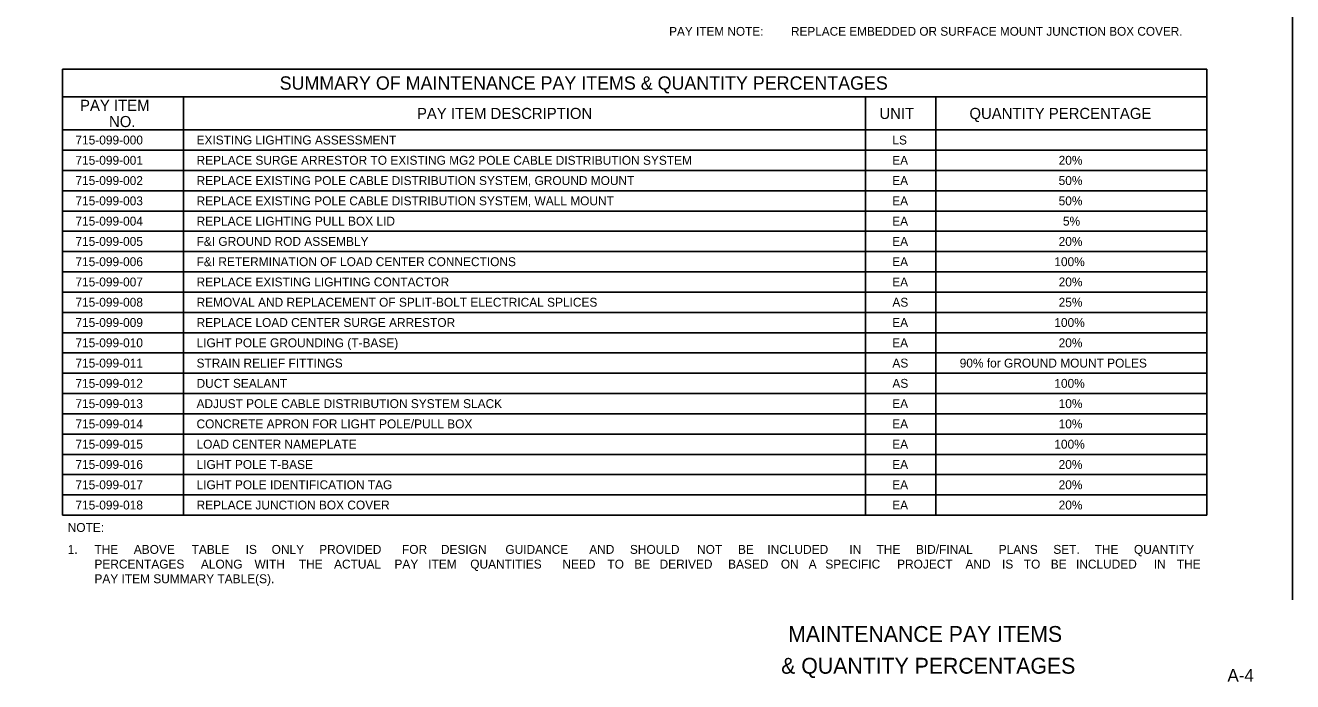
# Model space of a CAD drawing. Extents: x -55 to 2471539, y -90 to 3608906.
# Drawn here: x 543 to 1540, y -64 to 452 of the extents above; entities that cross this region are included whole.
import ezdxf

# ---------------------------------------------------------------- set-up
doc = ezdxf.new("R2010")
doc.units = 0
for name, color, linetype in [('NonPlottingEle_dp', 7, 'Continuous'), ('SumBoxBorder_dp', 7, 'Continuous'), ('SumBoxLines_dp', 7, 'Continuous'), ('SumBoxLinesMin_dp', 7, 'Continuous'), ('TextLabel', 7, 'Continuous'), ('TextMisc', 7, 'Continuous'), ('TextNotes', 7, 'Continuous'), ('TextShtNo', 7, 'Continuous')]:
    doc.layers.add(name, color=color, linetype=linetype)

msp = doc.modelspace()

# ---------------------------------------------------------------- linework, layer by layer
at = {"layer": 'NonPlottingEle_dp'}
msp.add_lwpolyline([(0, 0), (0, 960), (1540, 960), (1540, 0)], dxfattribs=at)
at = {"layer": 'SumBoxBorder_dp'}
for p, q in [((572.5, 417.37), (1472.5, 417.37)), ((572.5, 417.37), (572.5, 66.47)), ((1472.5, 417.37), (1472.5, 66.47)), ((572.5, 369.52), (1472.5, 369.52)), ((572.5, 369.52), (1472.5, 369.52)), ((572.5, 66.47), (1472.5, 66.47))]:
    msp.add_line(p, q, dxfattribs=at)
at = {"layer": 'SumBoxLines_dp'}
for p, q in [((572.5, 395.42), (1472.5, 395.42)), ((572.5, 395.42), (1472.5, 395.42)), ((667.75, 395.42), (667.75, 66.47)), ((667.75, 395.42), (667.75, 66.47)), ((1204, 395.42), (1204, 66.47)), ((1204, 395.42), (1204, 66.47)), ((1259.5, 395.42), (1259.5, 66.47)), ((1259.5, 395.42), (1259.5, 66.47)), ((572.5, 353.57), (1472.5, 353.57)), ((580.75, 353.57), (1204, 353.57))]:
    msp.add_line(p, q, dxfattribs=at)
at = {"layer": 'SumBoxLinesMin_dp'}
for p, q in [((1204, 353.57), (1259.5, 353.57)), ((572.5, 337.62), (1259.5, 337.62)), ((572.5, 337.62), (1472.5, 337.62)), ((572.5, 321.67), (1472.5, 321.67)), ((572.5, 321.67), (1472.5, 321.67)), ((572.5, 305.72), (1472.5, 305.72)), ((572.5, 305.72), (1472.5, 305.72)), ((572.5, 289.77), (1472.5, 289.77)), ((572.5, 289.77), (1472.5, 289.77)), ((572.5, 273.82), (1472.5, 273.82)), ((572.5, 273.82), (1472.5, 273.82)), ((572.5, 257.87), (1472.5, 257.87)), ((572.5, 257.87), (1472.5, 257.87)), ((572.5, 241.92), (1472.5, 241.92)), ((572.5, 241.92), (1472.5, 241.92)), ((572.5, 225.97), (1472.5, 225.97)), ((572.5, 225.97), (1472.5, 225.97)), ((572.5, 210.02), (1472.5, 210.02)), ((572.5, 210.02), (1472.5, 210.02)), ((572.5, 194.07), (1472.5, 194.07)), ((572.5, 194.07), (1472.5, 194.07)), ((572.5, 178.12), (1472.5, 178.12)), ((572.5, 178.12), (1472.5, 178.12)), ((572.5, 162.17), (1472.5, 162.17)), ((572.5, 162.17), (1472.5, 162.17)), ((572.5, 146.22), (1472.5, 146.22)), ((572.5, 146.22), (1472.5, 146.22)), ((572.5, 130.27), (1472.5, 130.27)), ((572.5, 130.27), (1472.5, 130.27)), ((572.5, 114.32), (1472.5, 114.32)), ((580.75, 114.32), (667.75, 114.32)), ((676, 114.32), (1472.5, 114.32)), ((572.5, 98.37), (1472.5, 98.37)), ((580.75, 98.37), (667.75, 98.37)), ((1259.5, 98.37), (1472.5, 98.37)), ((572.5, 82.42), (1472.5, 82.42)), ((580.75, 82.42), (667.75, 82.42)), ((1259.5, 82.42), (1472.5, 82.42))]:
    msp.add_line(p, q, dxfattribs=at)

# ---------------------------------------------------------------- texts
at = {"layer": 'TextLabel'}
for s, height, p in [('SUMMARY OF MAINTENANCE PAY ITEMS & QUANTITY PERCENTAGES', 10.5, (743.38, 401.15)), ('PAY ITEM', 8.75, (586.39, 384.47)), ('NO.', 8.75, (609.17, 371.72)), ('PAY ITEM DESCRIPTION', 8.75, (851.34, 378.1)), ('UNIT', 8.75, (1215.03, 378.1)), ('QUANTITY PERCENTAGE', 8.75, (1285.82, 378.1)), ('715-099-000', 7, (582.75, 358.05)), ('EXISTING LIGHTING ASSESSMENT', 7, (678, 358.05)), ('LS', 7, (1225.22, 358.05)), ('715-099-001', 7, (582.75, 342.1)), ('REPLACE SURGE ARRESTOR TO EXISTING MG2 POLE CABLE DISTRIBUTION SYSTEM', 7, (678, 342.1)), ('EA', 7, (1225.07, 342.1)), ('20%', 7, (1355.97, 342.1)), ('715-099-002', 7, (582.75, 326.15)), ('REPLACE EXISTING POLE CABLE DISTRIBUTION SYSTEM, GROUND MOUNT', 7, (678, 326.15)), ('EA', 7, (1225.07, 326.15)), ('50%', 7, (1355.97, 326.15)), ('715-099-003', 7, (582.75, 310.2)), ('REPLACE EXISTING POLE CABLE DISTRIBUTION SYSTEM, WALL MOUNT', 7, (678, 310.2)), ('EA', 7, (1225.07, 310.2)), ('50%', 7, (1355.97, 310.2)), ('715-099-004', 7, (582.75, 294.25)), ('REPLACE LIGHTING PULL BOX LID', 7, (678, 294.25)), ('EA', 7, (1225.07, 294.25)), ('5%', 7, (1359.35, 294.25)), ('715-099-005', 7, (582.75, 278.3)), ('F&I GROUND ROD ASSEMBLY', 7, (678, 278.3)), ('EA', 7, (1225.07, 278.3)), ('20%', 7, (1355.97, 278.3)), ('715-099-006', 7, (582.75, 262.35)), ('F&I RETERMINATION OF LOAD CENTER CONNECTIONS', 7, (678, 262.35)), ('EA', 7, (1225.07, 262.35)), ('100%', 7, (1352.58, 262.35)), ('715-099-007', 7, (582.75, 246.4)), ('REPLACE EXISTING LIGHTING CONTACTOR', 7, (678, 246.4)), ('EA', 7, (1225.07, 246.4)), ('20%', 7, (1355.97, 246.4)), ('715-099-008', 7, (582.75, 230.45)), ('REMOVAL AND REPLACEMENT OF SPLIT-BOLT ELECTRICAL SPLICES', 7, (678, 230.45)), ('AS', 7, (1225.22, 230.45)), ('25%', 7, (1355.97, 230.45)), ('715-099-009', 7, (582.75, 214.5)), ('REPLACE LOAD CENTER SURGE ARRESTOR', 7, (678, 214.5)), ('EA', 7, (1225.07, 214.5)), ('100%', 7, (1352.58, 214.5)), ('715-099-010', 7, (582.75, 198.55)), ('LIGHT POLE GROUNDING (T-BASE)', 7, (678, 198.55)), ('EA', 7, (1225.07, 198.55)), ('20%', 7, (1355.97, 198.55)), ('715-099-011', 7, (582.75, 182.6)), ('STRAIN RELIEF FITTINGS', 7, (678, 182.6)), ('AS', 7, (1225.22, 182.6)), ('90% for GROUND MOUNT POLES', 7, (1278.16, 182.6)), ('715-099-012', 7, (582.75, 166.65)), ('DUCT SEALANT', 7, (678, 166.65)), ('AS', 7, (1225.22, 166.65)), ('100%', 7, (1352.58, 166.65)), ('715-099-013', 7, (582.75, 150.7)), ('ADJUST POLE CABLE DISTRIBUTION SYSTEM SLACK', 7, (678, 150.7)), ('EA', 7, (1225.07, 150.7)), ('10%', 7, (1355.97, 150.7)), ('715-099-014', 7, (582.75, 134.75)), ('CONCRETE APRON FOR LIGHT POLE/PULL BOX', 7, (678, 134.75)), ('EA', 7, (1225.07, 134.75)), ('10%', 7, (1355.97, 134.75)), ('715-099-015', 7, (582.75, 118.8)), ('LOAD CENTER NAMEPLATE', 7, (678, 118.8)), ('EA', 7, (1225.07, 118.8)), ('100%', 7, (1352.58, 118.8)), ('715-099-016', 7, (582.75, 102.85)), ('LIGHT POLE T-BASE', 7, (678, 102.85)), ('EA', 7, (1225.07, 102.85)), ('20%', 7, (1355.97, 102.85)), ('715-099-017', 7, (582.75, 86.9)), ('LIGHT POLE IDENTIFICATION TAG', 7, (678, 86.9)), ('EA', 7, (1225.07, 86.9)), ('20%', 7, (1355.97, 86.9)), ('715-099-018', 7, (582.75, 70.95)), ('REPLACE JUNCTION BOX COVER', 7, (678, 70.95)), ('EA', 7, (1225.07, 70.95)), ('20%', 7, (1355.97, 70.95)), ('NOTE:', 7, (576.69, 53.3)), ('1.', 7, (576.69, 36.05)), ('THE ', 7, (597.69, 36.05)), ('ABOVE ', 7, (628.64, 36.05)), ('TABLE ', 7, (674.11, 36.05)), ('IS ', 7, (716.61, 36.05)), ('ONLY ', 7, (737.05, 36.05)), ('PROVIDED ', 7, (774.45, 36.05)), ('FOR ', 7, (839.57, 36.05)), ('DESIGN ', 7, (870.18, 36.05)), ('GUIDANCE ', 7, (920.88, 36.05)), ('AND ', 7, (986.82, 36.05)), ('SHOULD ', 7, (1018.8, 36.05)), ('NOT ', 7, (1071.62, 36.05)), ('BE ', 7, (1103.8, 36.05)), ('INCLUDED ', 7, (1126.9, 36.05)), ('IN ', 7, (1191.39, 36.05)), ('THE ', 7, (1212.78, 36.05)), ('BID/FINAL ', 7, (1243.73, 36.05)), ('PLANS ', 7, (1308.82, 36.05)), ('SET. ', 7, (1351.76, 36.05)), ('THE ', 7, (1384.24, 36.05)), ('QUANTITY ', 7, (1415.19, 36.05)), ('PERCENTAGES ', 7, (597.69, 24.5)), ('ALONG ', 7, (681.43, 24.5)), ('WITH ', 7, (723.56, 24.5)), ('THE ', 7, (758.47, 24.5)), ('ACTUAL ', 7, (786.15, 24.5)), ('PAY ', 7, (833.66, 24.5)), ('ITEM ', 7, (860.21, 24.5)), ('QUANTITIES ', 7, (893.24, 24.5)), ('NEED ', 7, (965.73, 24.5)), ('TO ', 7, (1001.11, 24.5)), ('BE ', 7, (1022.31, 24.5)), ('DERIVED ', 7, (1042.13, 24.5)), ('BASED ', 7, (1096.03, 24.5)), ('ON ', 7, (1137.49, 24.5)), ('A ', 7, (1159.4, 24.5)), ('SPECIFIC ', 7, (1172.49, 24.5)), ('PROJECT ', 7, (1228.94, 24.5)), ('AND ', 7, (1282.7, 24.5)), ('IS ', 7, (1311.41, 24.5)), ('TO ', 7, (1328.57, 24.5)), ('BE ', 7, (1349.78, 24.5)), ('INCLUDED ', 7, (1369.6, 24.5)), ('IN ', 7, (1430.81, 24.5)), ('THE ', 7, (1448.92, 24.5)), ('PAY ITEM SUMMARY TABLE(S).', 7, (597.69, 12.95))]:
    msp.add_text(s, height=height, dxfattribs=at).set_placement(p)
at = {"layer": 'TextMisc'}
for s, p in [('MAINTENANCE PAY ITEMS', (1143.25, -33.24)), ('& QUANTITY PERCENTAGES', (1137.8, -58.24))]:
    msp.add_text(s, height=12.5, dxfattribs=at).set_placement(p)
at = {"layer": 'TextNotes'}
for s, p in [('PAY ITEM NOTE: ', (1049.65, 443.58)), ('REPLACE EMBEDDED OR SURFACE MOUNT JUNCTION BOX COVER.', (1145.5, 443.58))]:
    msp.add_text(s, height=6.93, dxfattribs=at).set_placement(p)
at = {"layer": 'TextShtNo'}
msp.add_text(' A-4 ', height=10, dxfattribs=at).set_placement((1484.99, -64.49))

doc.saveas('drawing.dxf')
